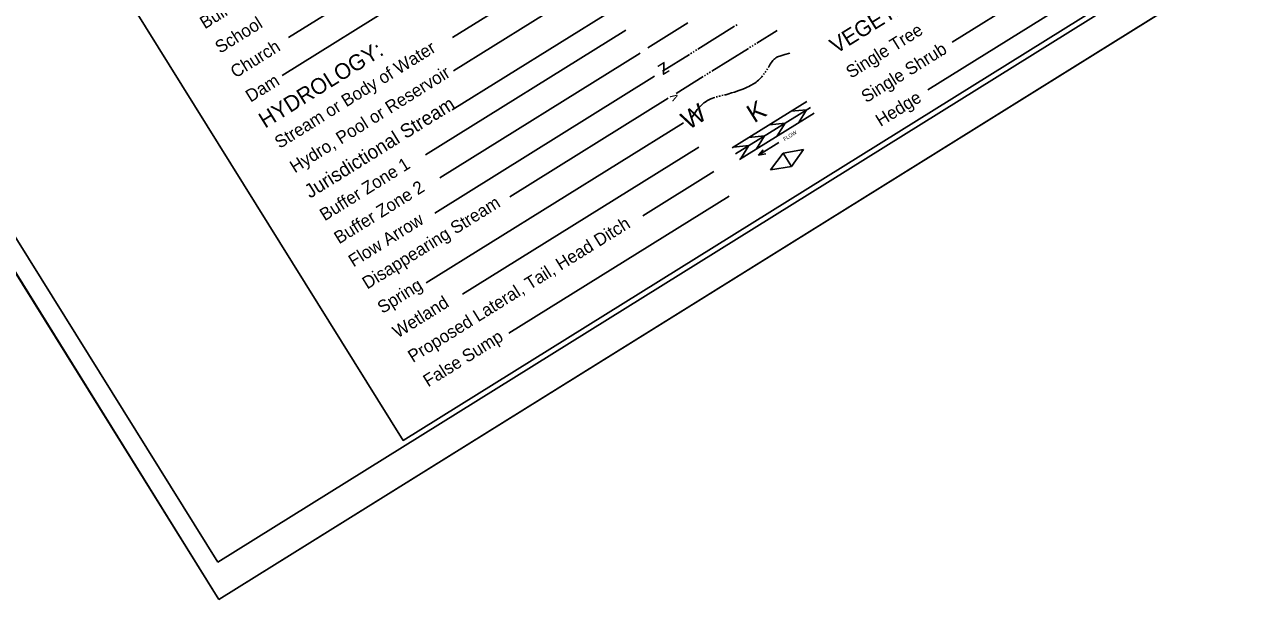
# Model space of a CAD drawing. Extents: x 2046091 to 2048102, y 759061 to 760885.
# Drawn here: x 2046537 to 2047393, y 759061 to 759460 of the extents above; entities that cross this region are included whole.
import ezdxf

# ---------------------------------------------------------------- set-up
doc = ezdxf.new("R2010")
doc.units = 0
for name, color, linetype in [('Sheet Cutting Line CELL', 7, 'Continuous'), ('Sheet Plot Border Inside CELL', 7, 'Continuous'), ('Sheet Plot Border Outside CELL', 7, 'Continuous'), ('Sheet Symbology CELL', 7, 'Continuous')]:
    doc.layers.add(name, color=color, linetype=linetype)

msp = doc.modelspace()

# ---------------------------------------------------------------- linework, layer by layer
at = {"layer": 'Sheet Cutting Line CELL'}
for p, q in [((2046090.62, 759994.95), (2046672.2, 759061.26)), ((2046672.2, 759061.26), (2048101.59, 759951.6))]:
    msp.add_line(p, q, dxfattribs=at)
at = {"layer": 'Sheet Plot Border Inside CELL'}
msp.add_lwpolyline([(2046671.37, 759087.19), (2048085.9, 759968.28), (2047528.06, 760863.85), (2046113.53, 759982.76)], close=True, dxfattribs=at)
at = {"layer": 'Sheet Plot Border Outside CELL'}
msp.add_lwpolyline([(2046672.2, 759061.26), (2048101.59, 759951.6), (2047520.01, 760885.29), (2046090.62, 759994.95)], close=True, dxfattribs=at)
at = {"layer": 'Sheet Symbology CELL'}
for p, q in [((2046896.9, 759561.32), (2046720.59, 759451.51)), ((2046907.47, 759544.35), (2046716.13, 759425.16)), ((2047335.07, 759544), (2047181.33, 759448.24)), ((2047345.02, 759527.51), (2047164.49, 759415.06)), ((2046923.41, 759506.92), (2046834.29, 759451.4)), ((2046933.98, 759489.94), (2046835.19, 759428.41)), ((2046945.93, 759470.76), (2046834.22, 759401.18)), ((2046954.72, 759456.66), (2046815.72, 759370.08)), ((2046970.05, 759444.36), (2046997.89, 759461.7)), ((2047004.83, 759443.41), (2047030.3, 759459.27)), ((2047031.15, 759459.8), (2047032, 759460.33)), ((2047045.82, 759447.6), (2047059.8, 759456.31)), ((2046964.69, 759440.64), (2046825.7, 759354.06)), ((2046980.2, 759428.07), (2046998.89, 759439.71)), ((2046999.74, 759440.24), (2047000.59, 759440.77)), ((2047001.44, 759441.3), (2047002.29, 759441.83)), ((2047003.14, 759442.36), (2047003.99, 759442.88)), ((2047014.41, 759428.03), (2047039.88, 759443.9)), ((2047040.73, 759444.42), (2047041.58, 759444.95)), ((2047042.42, 759445.48), (2047043.27, 759446.01)), ((2047044.12, 759446.54), (2047044.97, 759447.07)), ((2046974.67, 759424.62), (2046822.02, 759329.54)), ((2046989.78, 759412.69), (2047008.47, 759424.33)), ((2047009.32, 759424.86), (2047010.17, 759425.39)), ((2047011.02, 759425.92), (2047011.87, 759426.45)), ((2047012.72, 759426.98), (2047013.56, 759427.51)), ((2047050.28, 759425.66), (2047050.86, 759426.47)), ((2047051.47, 759427.27), (2047052.04, 759428.08)), ((2046984.25, 759409.25), (2046874.32, 759340.77)), ((2047021.4, 759411.12), (2047022.38, 759411.35)), ((2047028.68, 759374.77), (2047080.47, 759407.03)), ((2047030.99, 759370.56), (2047083.01, 759402.96)), ((2047033.68, 759366.75), (2047085.46, 759399.01)), ((2047069.68, 759400.31), (2047080.36, 759401.31)), ((2047080.36, 759401.31), (2047074.9, 759392.43)), ((2046994.82, 759392.27), (2046816.17, 759280.99)), ((2047054.62, 759390.93), (2047065.5, 759392.05)), ((2047065.5, 759392.05), (2047059.91, 759383.1)), ((2047040.23, 759381.97), (2047051.08, 759383.07)), ((2047051.08, 759383.07), (2047045.5, 759374.12)), ((2047005.4, 759375.29), (2046841.4, 759273.14)), ((2047029.44, 759375.25), (2047040.29, 759376.35)), ((2047040.29, 759376.35), (2047034.67, 759367.37)), ((2047046.88, 759369.67), (2047061.01, 759378.48)), ((2047046.88, 759369.67), (2047050.24, 759373.36)), ((2047063.94, 759371.25), (2047055.21, 759359.59)), ((2047078.16, 759373.59), (2047063.94, 759371.25)), ((2047069.78, 759361.87), (2047063.94, 759371.25)), ((2047069.78, 759361.87), (2047078.16, 759373.59)), ((2047046.88, 759369.67), (2047051.98, 759370.56)), ((2047015.97, 759358.32), (2046966.59, 759327.56)), ((2047055.21, 759359.59), (2047069.78, 759361.87)), ((2047026.55, 759341.34), (2046873.53, 759246.03))]:
    msp.add_line(p, q, dxfattribs=at)
msp.add_lwpolyline([(2047518.8, 760855.08), (2046245.59, 760062.02), (2046800.2, 759171.64), (2048073.4, 759964.7)], close=True, dxfattribs=at)
for points in [[(2047053.7, 759430.59), (2047053.98, 759431.05), (2047055.1, 759432.95), (2047055.69, 759433.9), (2047056.35, 759434.81), (2047056.88, 759435.44), (2047057.38, 759435.96), (2047057.85, 759436.4), (2047058.27, 759436.76), (2047059.06, 759437.33), (2047059.68, 759437.72), (2047060.15, 759437.97), (2047060.89, 759438.3), (2047061.65, 759438.56), (2047065.18, 759439.61), (2047068.7, 759440.65)], [(2047023.36, 759411.57), (2047024.14, 759411.75), (2047025.55, 759412.14), (2047028.21, 759412.96), (2047030.2, 759413.6), (2047033.14, 759414.61), (2047036.08, 759415.69), (2047037.68, 759416.33), (2047039.07, 759416.93), (2047040.28, 759417.51), (2047041.32, 759418.03), (2047042.2, 759418.53), (2047042.98, 759418.98), (2047044.28, 759419.82), (2047045.23, 759420.5), (2047045.92, 759421.05), (2047046.91, 759421.89), (2047047.85, 759422.8), (2047048.53, 759423.53), (2047049.11, 759424.18), (2047049.66, 759424.88)], [(2047052.62, 759428.9), (2047052.74, 759429.08), (2047053.18, 759429.74)], [(2047000.36, 759395.72), (2047002.14, 759398.23), (2047003.93, 759400.75), (2047004.39, 759401.36), (2047005.23, 759402.4), (2047005.92, 759403.14), (2047006.98, 759404.2), (2047008.09, 759405.2), (2047009.06, 759405.98), (2047009.95, 759406.64), (2047010.75, 759407.17), (2047011.48, 759407.62), (2047012.78, 759408.33), (2047013.79, 759408.82), (2047014.55, 759409.15), (2047015.73, 759409.61), (2047016.56, 759409.89)], [(2047017.52, 759410.18), (2047017.99, 759410.31), (2047018.48, 759410.44)], [(2047019.45, 759410.67), (2047019.88, 759410.78), (2047020.43, 759410.9)]]:
    msp.add_lwpolyline(points, dxfattribs=at)

# ---------------------------------------------------------------- texts
for s, height, rotation, p in [('VEGETATION:', 11, 31.91803, (2047100.82, 759439.86)), ('Building', 8.75, 31.91803, (2046662.41, 759457.08)), ('School', 8.75, 31.91803, (2046672.98, 759440.09)), ('Single Tree', 8.75, 31.91803, (2047111.15, 759422.76)), ('Church', 8.75, 31.91803, (2046683.67, 759422.97)), ('HYDROLOGY:', 11, 31.91803, (2046704.22, 759388.09)), ('Stream or Body of Water', 8.75, 31.91803, (2046714.33, 759374.02)), ('Single Shrub', 8.75, 31.91803, (2047121.73, 759405.78)), ('z', 10, 211.91805, (2046981.81, 759434.96)), ('Dam', 8.75, 31.91803, (2046694.14, 759406.15)), ('Hydro, Pool or Reservoir', 8.75, 31.91803, (2046724.9, 759357.04)), ('Jurisdictional Stream', 9.646, 31.91803, (2046735.47, 759339.44)), ('v', 6.6, 121.67718, (2046991.75, 759409.52)), ('W', 12.75, 31.91803, (2046998.32, 759386.94)), ('K', 12.75, 31.91803, (2047043.91, 759391.77)), ('Hedge', 8.75, 31.91803, (2047131.68, 759389.29)), ('FLOW', 2.593, 31.91803, (2047065.07, 759379.41)), ('Buffer Zone 1', 8.75, 31.91803, (2046745.63, 759323.76)), ('Buffer Zone 2', 8.75, 31.91803, (2046755.61, 759307.74)), ('Disappearing Stream', 8.75, 31.91803, (2046775.16, 759276.35)), ('Flow Arrow', 8.75, 31.91803, (2046765.59, 759291.72)), ('Proposed Lateral, Tail, Head Ditch', 8.75, 31.91803, (2046806.89, 759225.42)), ('Spring', 8.75, 31.91803, (2046785.74, 759259.37)), ('Wetland', 8.75, 31.91803, (2046796.31, 759242.39)), ('False Sump', 8.75, 31.91803, (2046817.46, 759208.44))]:
    msp.add_text(s, height=height, rotation=rotation, dxfattribs=at).set_placement(p)

doc.saveas('drawing.dxf')
